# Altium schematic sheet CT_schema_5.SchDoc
size 278 x 170 mm
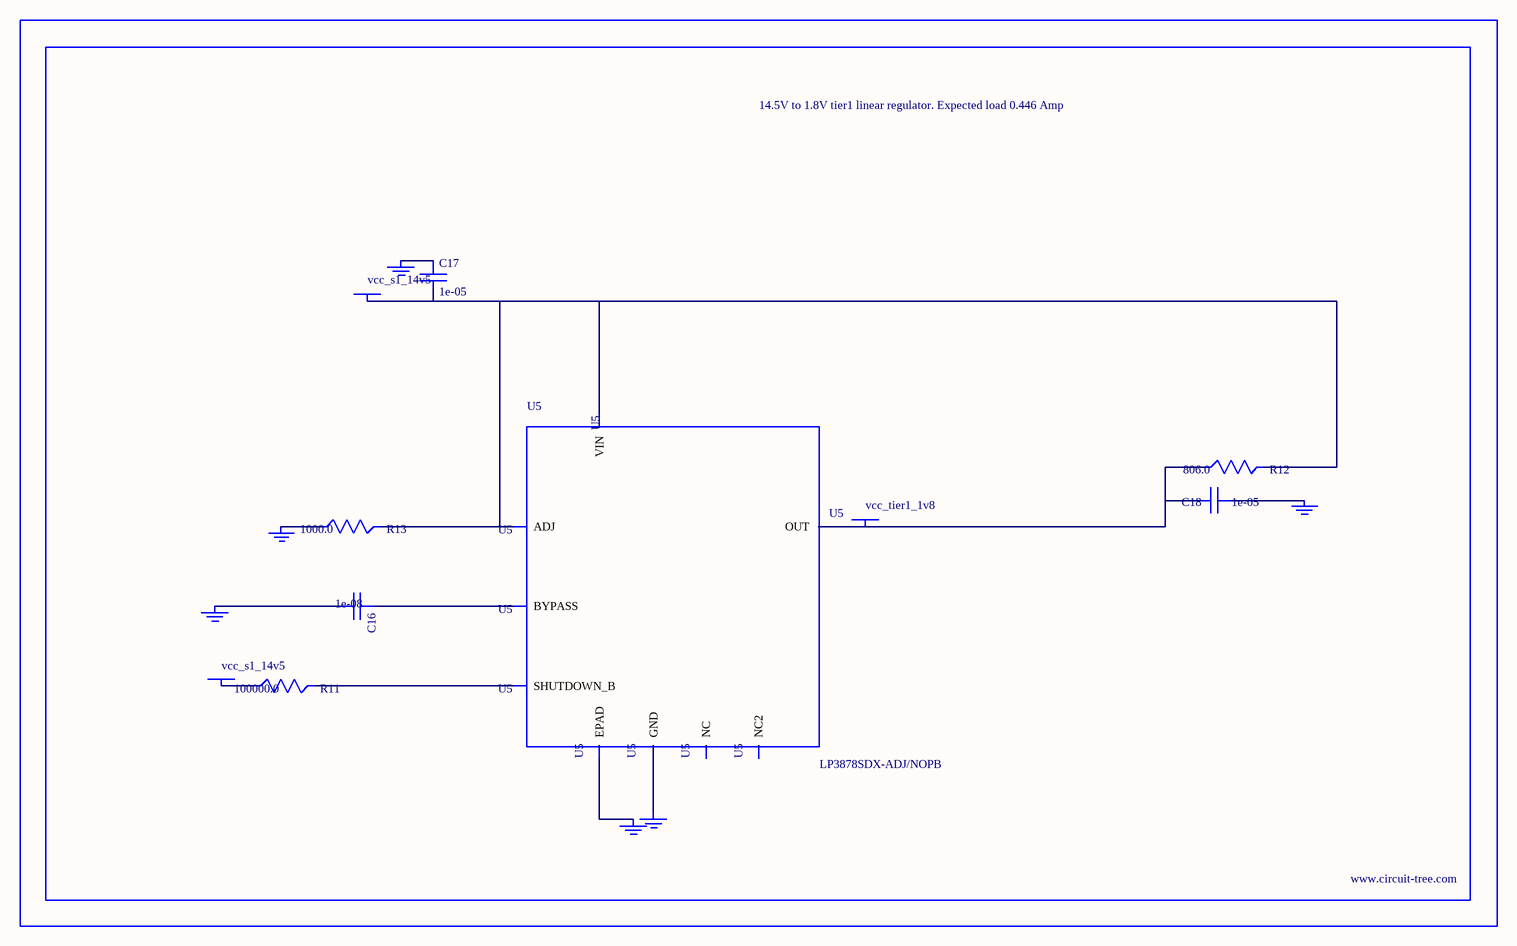
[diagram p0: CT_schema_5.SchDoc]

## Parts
BORDER4  (no value)
C16  1e-08  [C0402]
C17  1e-05  [C1210]
C18  1e-05  [C0805]
GND_INSTANCE_4_0  (no value)
GND_INSTANCE_4_1  (no value)
GND_INSTANCE_4_2  (no value)
GND_INSTANCE_4_3  (no value)
GND_INSTANCE_4_4  (no value)
GND_INSTANCE_4_5  (no value)
POWER_INSTANCE_4_0  vcc_s1_14v5
POWER_INSTANCE_4_1  vcc_s1_14v5
POWER_INSTANCE_4_2  vcc_tier1_1v8
R11  100000.0  [R0603]
R12  806.0  [R0603]
R13  1000.0  [R0603]
U5  LP3878SDX-ADJ/NOPB  [WSON-8]

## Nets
NetC16_1: C16.1 U5.1(BYPASS)
NetC16_2: C16.2 GND_INSTANCE_4_0.0(GND)
NetC17_1: C17.1 GND_INSTANCE_4_1.0(GND)
NetC17_2: C17.2 POWER_INSTANCE_4_0.0(PWR) R12.2 R13.2 U5.4(VIN) U5.6(ADJ)
NetC18_1: C18.1 GND_INSTANCE_4_2.0(GND)
NetC18_2: C18.2 POWER_INSTANCE_4_2.0(PWR) R12.1 U5.5(OUT)
NetGND_INSTANCE_4_3_0: GND_INSTANCE_4_3.0(GND) R13.1
NetGND_INSTANCE_4_4_0: GND_INSTANCE_4_4.0(GND) U5.PAD(EPAD)
NetGND_INSTANCE_4_5_0: GND_INSTANCE_4_5.0(GND) U5.3(GND)
NetPOWER_INSTANCE_4_1_0: POWER_INSTANCE_4_1.0(PWR) R11.1
NetR11_2: R11.2 U5.8(SHUTDOWN_B)

Not connected (* = marked no-connect by the designer): U5 2(NC) 7(NC2)

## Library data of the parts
BORDER4 = BORDER_PAGE4
C16 = C0402C103K3RAC
C17 = C1210C106K5PACTU
C18 = GRM219R60J106ME19D
GND_INSTANCE_4_0-GND_INSTANCE_4_5 = GND
POWER_INSTANCE_4_0-POWER_INSTANCE_4_2 = PWR
R11 = RC0603JR-07100KL
R12 = ERJ-3EKF8060V
R13 = RC0603JR-071KL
